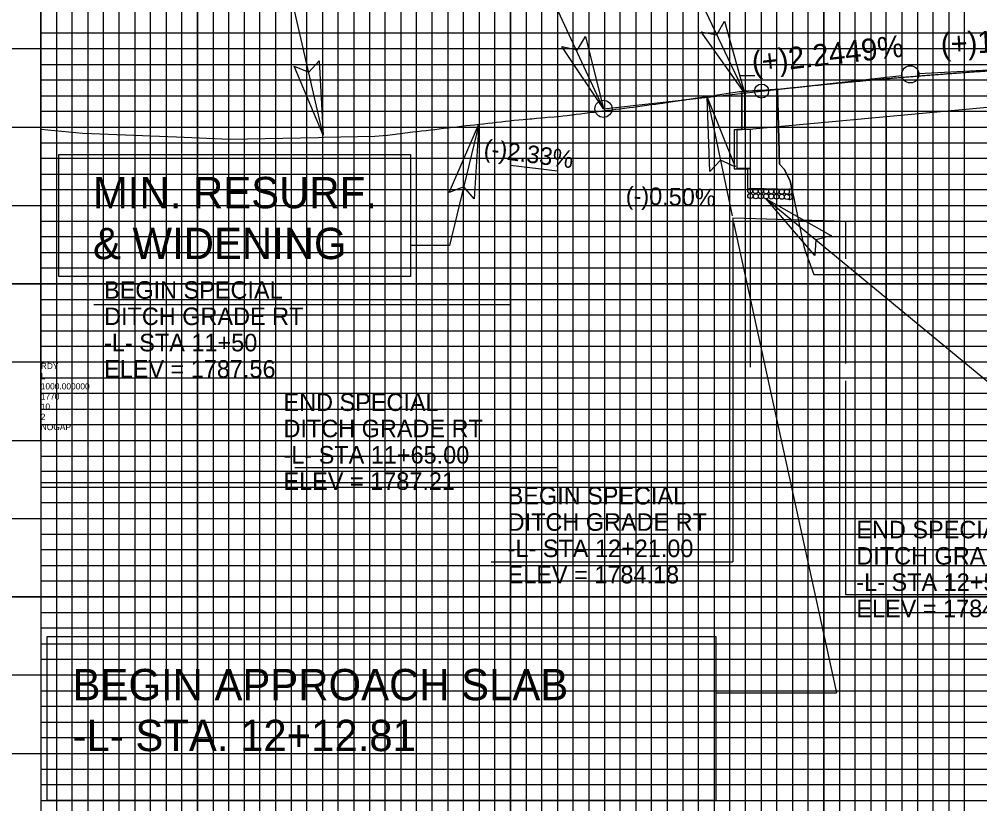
# Model space of a CAD drawing. Extents: x 572269 to 579912, y -56875 to -49627.
# Drawn here: x 573877.8 to 574184.5, y -53513.8 to -53263.2 of the extents above; entities that cross this region are included whole.
import ezdxf

# ---------------------------------------------------------------- set-up
doc = ezdxf.new("R2010")
doc.units = 0
for name, color, linetype in [('Exist Profile Cell', 7, 'Continuous'), ('Exist Vertical Profile Ground Line', 7, 'Continuous'), ('Pattern 9', 7, 'Continuous'), ('Prop Grid Mask', 7, 'Continuous'), ('Prop Hatching', 7, 'Continuous'), ('Prop PFL Text', 7, 'Continuous'), ('Prop Rip Rap Related Quantities Text', 7, 'Continuous'), ('Prop Roadway Bridge', 7, 'Continuous'), ('Prop Vertical Profile Curve Label', 7, 'Continuous'), ('Prop Vertical Profile Ditch Grade Right', 7, 'Continuous'), ('Prop Vertical Profile Ditch Grade Right Label', 7, 'Continuous'), ('Prop Vertical Profile Grade', 7, 'Continuous'), ('Prop Vertical Profile Grade Label', 7, 'Continuous'), ('Prop VPI Label', 7, 'Continuous'), ('Scratch_Level_0', 7, 'Continuous'), ('Scratch_Level_6', 7, 'Continuous'), ('Sheet Cutting Line CELL', 7, 'Continuous'), ('Sheet DOT Grid CELL', 7, 'Continuous'), ('Sheet Layout Profile Border', 7, 'Continuous'), ('Sheet Profile Grid Major CELL', 7, 'Continuous'), ('Sheet Profile Grid Middle CELL', 7, 'Continuous'), ('Sheet Profile Grid Minor CELL', 7, 'Continuous'), ('Typical Terminator CELL', 7, 'Continuous')]:
    doc.layers.add(name, color=color, linetype=linetype)

# ---------------------------------------------------------------- blocks, each defined once
blk = doc.blocks.new('TERMINATOR')
at = {"layer": 'Typical Terminator CELL'}
blk.add_lwpolyline([(-0.4687, 0.0807), (0, 0), (-0.4713, -0.0833), (-0.4114, 0)], close=True, dxfattribs=at)
blk = doc.blocks.new('PROFILE SHEET SINGLE')
at = {"layer": 'Sheet DOT Grid CELL'}
for p, q in [((1, 21), (1, 0.5)), ((2, 21), (2, 0.5)), ((3, 21), (3, 0.5)), ((4, 21), (4, 0.5)), ((5, 21), (5, 0.5)), ((6, 21), (6, 0.5)), ((0, 10.5), (30, 10.5)), ((0, 9.5), (30, 9.5)), ((0, 8.5), (30, 8.5)), ((0, 7.5), (30, 7.5)), ((0, 6.5), (30, 6.5))]:
    blk.add_line(p, q, dxfattribs=at)
at = {"layer": 'Sheet Profile Grid Major CELL'}
for points in [[(1, 21), (1, 0.5), (2, 0.5), (2, 21)], [(3, 21), (3, 0.5), (4, 0.5), (4, 21)], [(5, 21), (5, 0.5), (6, 0.5), (6, 21)], [(30, 9.5), (0, 9.5), (0, 10.5), (30, 10.5)], [(30, 7.5), (0, 7.5), (0, 8.5), (30, 8.5)], [(30, 5.5), (0, 5.5), (0, 6.5), (30, 6.5)]]:
    blk.add_lwpolyline(points, dxfattribs=at)
at = {"layer": 'Sheet Profile Grid Middle CELL'}
for points in [[(1.5, 0.5), (1.5, 21)], [(2.5, 21), (2.5, 0.5), (3.5, 0.5), (3.5, 21)], [(4.5, 21), (4.5, 0.5), (5.5, 0.5), (5.5, 21)], [(6.5, 21), (6.5, 0.5), (7.5, 0.5), (7.5, 21)], [(30, 11), (0, 11), (0, 10), (30, 10)], [(30, 9), (0, 9), (0, 8), (30, 8)], [(30, 7), (0, 7), (0, 6), (30, 6)]]:
    blk.add_lwpolyline(points, dxfattribs=at)
at = {"layer": 'Sheet Profile Grid Minor CELL'}
for points in [[(1.1, 21), (1.1, 0.5), (1.2, 0.5), (1.2, 21)], [(1.3, 21), (1.3, 0.5), (1.4, 0.5), (1.4, 21)], [(1.6, 21), (1.6, 0.5), (1.7, 0.5), (1.7, 21)], [(1.8, 21), (1.8, 0.5), (1.9, 0.5), (1.9, 21)], [(2.1, 21), (2.1, 0.5), (2.2, 0.5), (2.2, 21)], [(2.3, 21), (2.3, 0.5), (2.4, 0.5), (2.4, 21)], [(2.6, 21), (2.6, 0.5), (2.7, 0.5), (2.7, 21)], [(2.8, 21), (2.8, 0.5), (2.9, 0.5), (2.9, 21)], [(3.1, 21), (3.1, 0.5), (3.2, 0.5), (3.2, 21)], [(3.3, 21), (3.3, 0.5), (3.4, 0.5), (3.4, 21)], [(3.6, 21), (3.6, 0.5), (3.7, 0.5), (3.7, 21)], [(3.8, 21), (3.8, 0.5), (3.9, 0.5), (3.9, 21)], [(4.1, 21), (4.1, 0.5), (4.2, 0.5), (4.2, 21)], [(4.3, 21), (4.3, 0.5)], [(4.3, 0.5), (4.4, 0.5), (4.4, 21)], [(4.6, 21), (4.6, 0.5), (4.7, 0.5), (4.7, 21)], [(4.8, 21), (4.8, 0.5), (4.9, 0.5), (4.9, 21)], [(5.1, 21), (5.1, 0.5), (5.2, 0.5), (5.2, 21)], [(5.3, 21), (5.3, 0.5), (5.4, 0.5), (5.4, 21)], [(5.6, 21), (5.6, 0.5), (5.7, 0.5), (5.7, 21)], [(5.8, 21), (5.8, 0.5), (5.9, 0.5), (5.9, 21)], [(6.1, 21), (6.1, 0.5), (6.2, 0.5), (6.2, 21)], [(6.3, 21), (6.3, 0.5), (6.4, 0.5), (6.4, 21)], [(6.6, 21), (6.6, 0.5), (6.7, 0.5), (6.7, 21)], [(6.8, 21), (6.8, 0.5), (6.9, 0.5), (6.9, 21)], [(29, 11.1), (1, 11.1), (1, 10.9), (29, 10.9)], [(29, 10.8), (1, 10.8), (1, 10.7), (29, 10.7)], [(29, 10.6), (1, 10.6)], [(1, 10.4), (29, 10.4)], [(29, 10.3), (1, 10.3), (1, 10.2), (29, 10.2)], [(29, 10.1), (1, 10.1), (1, 9.9), (29, 9.9)], [(29, 9.8), (1, 9.8), (1, 9.7), (29, 9.7)], [(29, 9.6), (1, 9.6), (1, 9.4), (29, 9.4)], [(29, 9.3), (1, 9.3), (1, 9.2), (29, 9.2)], [(29, 9.1), (1, 9.1), (1, 8.9), (29, 8.9)], [(29, 8.8), (1, 8.8), (1, 8.7), (29, 8.7)], [(29, 8.6), (1, 8.6), (1, 8.4), (29, 8.4)], [(29, 8.3), (1, 8.3), (1, 8.2), (29, 8.2)], [(29, 8.1), (1, 8.1), (1, 7.9), (29, 7.9)], [(29, 7.8), (1, 7.8), (1, 7.7), (29, 7.7)], [(29, 7.6), (1, 7.6), (1, 7.4), (29, 7.4)], [(29, 7.3), (1, 7.3), (1, 7.2), (29, 7.2)], [(29, 7.1), (1, 7.1), (1, 6.9), (29, 6.9)], [(29, 6.8), (1, 6.8), (1, 6.7), (29, 6.7)], [(29, 6.6), (1, 6.6), (1, 6.4), (29, 6.4)], [(29, 6.3), (1, 6.3), (1, 6.2), (29, 6.2)]]:
    blk.add_lwpolyline(points, dxfattribs=at)

msp = doc.modelspace()

# ---------------------------------------------------------------- linework, layer by layer
at = {"layer": 'Exist Profile Cell'}
for q in [(573884.69, -53147.71), (574399.37, -53397.71), (573884.69, -53397.71)]:
    msp.add_line((573884.69, -53397.71), q, dxfattribs=at)
at = {"layer": 'Exist Vertical Profile Ground Line'}
for points in [[(573884.69, -53298.32), (573889.23, -53298.76), (573898.12, -53299.62), (573928.04, -53300.85), (573945.11, -53301.55), (573973.3, -53301.02), (573975.11, -53300.91), (573991.41, -53300.56), (573993.98, -53300.4), (573995.42, -53300.23), (574003.48, -53299.25), (574004.89, -53299.08), (574006.3, -53298.91), (574007.71, -53298.74), (574009.12, -53298.57), (574010.52, -53298.41), (574011.93, -53298.24), (574013.34, -53298.07), (574014.75, -53297.91), (574016.16, -53297.74), (574017.57, -53297.57), (574018.98, -53297.41), (574020.54, -53297.23), (574021.8, -53297.09), (574023.21, -53296.93), (574024.62, -53296.77), (574026.03, -53296.61), (574027.44, -53296.46), (574028.85, -53296.3), (574030.26, -53296.14), (574031.67, -53295.98), (574033.08, -53295.82), (574034.49, -53295.66), (574035.01, -53295.61), (574035.9, -53295.53), (574037.31, -53295.4), (574038.72, -53295.27), (574040.12, -53295.14), (574040.81, -53295.08), (574041.53, -53295.01), (574042.94, -53294.87), (574044.35, -53294.73), (574045.76, -53294.59), (574047.17, -53294.47), (574048.12, -53294.49), (574048.58, -53294.44), (574049.99, -53294.29), (574051.4, -53294.13), (574052.81, -53293.98), (574054.22, -53293.82), (574054.54, -53293.78), (574055.05, -53293.64), (574055.63, -53293.58), (574057.04, -53293.41), (574058.45, -53293.25), (574059.86, -53293.08), (574061.54, -53292.89), (574062.68, -53292.7), (574063.17, -53292.62), (574064.09, -53292.51), (574065.5, -53292.34), (574066.91, -53292.17), (574068.32, -53292), (574069.72, -53291.83), (574071.13, -53291.64), (574072.54, -53291.46), (574073.95, -53291.28), (574075.36, -53291.1), (574076.77, -53290.92), (574078.18, -53290.72), (574079.59, -53290.52), (574081, -53290.33), (574082.41, -53290.14), (574083.31, -53290.01), (574083.82, -53289.96), (574085.23, -53289.75), (574086.64, -53289.54), (574088.05, -53289.34), (574089.46, -53289.13), (574090.55, -53288.97), (574090.87, -53288.92), (574092.28, -53288.71), (574093.69, -53288.49), (574095.1, -53288.27), (574096.51, -53288.06), (574097.3, -53287.94), (574098.07, -53287.86), (574099.32, -53287.66), (574100.73, -53287.44), (574102.14, -53287.21), (574103.55, -53286.99), (574104.96, -53286.76), (574106.37, -53286.53), (574107.78, -53286.3), (574108.41, -53286.31), (574109.19, -53286.27), (574110.6, -53286.2), (574112.01, -53286.12), (574113.42, -53286.05), (574114.83, -53285.97), (574116.24, -53285.89), (574117.65, -53285.82), (574119.06, -53285.72), (574119.95, -53285.57), (574120.55, -53309.54), (574122.17, -53311.24), (574123.29, -53313.5), (574123.96, -53314.87), (574124.7, -53318.37), (574126.11, -53325.08), (574127.52, -53331.81), (574128.35, -53335.77), (574128.92, -53337.47), (574130.33, -53341.53), (574131.58, -53344.81), (574131.96, -53344.81), (574133.15, -53344.81), (574134.56, -53344.81), (574135.97, -53344.81), (574137.38, -53344.81), (574138.79, -53344.81), (574140.2, -53344.81), (574141.61, -53344.81), (574143.02, -53344.81), (574144.43, -53344.81), (574145.54, -53344.81), (574145.84, -53344.81), (574147.25, -53344.81), (574148.66, -53344.81), (574150.07, -53344.81), (574151.48, -53344.81), (574152.07, -53344.81), (574152.89, -53344.81), (574153.83, -53344.81), (574154.3, -53344.81), (574155.71, -53344.81), (574164.26, -53344.81), (574189.32, -53344.81)], [(573884.69, -53298.32), (573889.23, -53298.76), (573898.12, -53299.62), (573928.04, -53300.85), (573945.11, -53301.55), (573973.3, -53301.02), (573975.11, -53300.91), (573991.41, -53300.56), (573993.98, -53300.4), (573995.42, -53300.23), (574003.48, -53299.25), (574004.89, -53299.08), (574006.3, -53298.91), (574007.71, -53298.74), (574009.12, -53298.57), (574010.52, -53298.41), (574011.93, -53298.24), (574013.34, -53298.07), (574014.75, -53297.91), (574016.16, -53297.74), (574017.57, -53297.57), (574018.98, -53297.41), (574020.54, -53297.23), (574021.8, -53297.09), (574023.21, -53296.93), (574024.62, -53296.77), (574026.03, -53296.61), (574027.44, -53296.46), (574028.85, -53296.3), (574030.26, -53296.14), (574031.67, -53295.98), (574033.08, -53295.82), (574034.49, -53295.66), (574035.01, -53295.61), (574035.9, -53295.53), (574037.31, -53295.4), (574038.72, -53295.27), (574040.12, -53295.14), (574040.81, -53295.08), (574041.53, -53295.01), (574042.94, -53294.87), (574044.35, -53294.73), (574045.76, -53294.59), (574047.17, -53294.47), (574048.12, -53294.49), (574048.58, -53294.44), (574049.99, -53294.29), (574051.4, -53294.13), (574052.81, -53293.98), (574054.22, -53293.82), (574054.54, -53293.78), (574055.05, -53293.64), (574055.63, -53293.58), (574057.04, -53293.41), (574058.45, -53293.25), (574059.86, -53293.08), (574061.54, -53292.89), (574062.68, -53292.7), (574063.17, -53292.62), (574064.09, -53292.51), (574065.5, -53292.34), (574066.91, -53292.17), (574068.32, -53292), (574069.72, -53291.83), (574071.13, -53291.64), (574072.54, -53291.46), (574073.95, -53291.28), (574075.36, -53291.1), (574076.77, -53290.92), (574078.18, -53290.72), (574079.59, -53290.52), (574081, -53290.33), (574082.41, -53290.14), (574083.31, -53290.01), (574083.82, -53289.96), (574085.23, -53289.75), (574086.64, -53289.54), (574088.05, -53289.34), (574089.46, -53289.13), (574090.55, -53288.97), (574090.87, -53288.92), (574092.28, -53288.71), (574093.69, -53288.49), (574095.1, -53288.27), (574096.51, -53288.06), (574097.3, -53287.94), (574098.07, -53287.86), (574099.32, -53287.66), (574100.73, -53287.44), (574102.14, -53287.21), (574103.55, -53286.99), (574104.96, -53286.76), (574106.37, -53286.53), (574107.78, -53286.3), (574108.41, -53286.31), (574109.19, -53286.27), (574110.6, -53286.2), (574112.01, -53286.12), (574113.42, -53286.05), (574114.83, -53285.97), (574116.24, -53285.89), (574117.65, -53285.82), (574119.06, -53285.72), (574119.95, -53285.57), (574120.55, -53309.54), (574122.17, -53311.24), (574123.29, -53313.5), (574123.96, -53314.87), (574124.7, -53318.37), (574125.99, -53324.54)]]:
    msp.add_lwpolyline(points, dxfattribs=at)
at = {"layer": 'Pattern 9'}
for p, q in [((574108.5, -53286.36), (574108.5, -53286.9)), ((574108.5, -53286.9), (574108.5, -53298.54)), ((574109.43, -53286.26), (574109.43, -53298.44)), ((574112.49, -53286.15), (574111.08, -53286.23)), ((574113.9, -53286.08), (574112.49, -53286.15)), ((574115.31, -53286), (574113.9, -53286.08)), ((574119.96, -53285.62), (574118.13, -53285.82)), ((574120.55, -53309.54), (574119.96, -53285.62)), ((574108.5, -53298.54), (574106.07, -53298.54)), ((574106.07, -53298.54), (574106.07, -53311.04)), ((574109.43, -53298.44), (574107, -53298.44)), ((574107, -53298.44), (574107, -53310.94)), ((574106.07, -53311.04), (574110.32, -53311.04)), ((574107, -53310.94), (574111.25, -53310.94)), ((574110.32, -53311.04), (574110.32, -53317.32)), ((574111.25, -53310.94), (574111.25, -53317.21)), ((574122.17, -53311.24), (574120.55, -53309.54)), ((574110.32, -53317.32), (574124.52, -53317.55)), ((574111.25, -53317.21), (574124.52, -53317.55))]:
    msp.add_line(p, q, dxfattribs=at)
for points in [[(574111.08, -53286.23), (574109.67, -53286.3), (574108.5, -53286.36)], [(574124.52, -53317.55), (574123.96, -53314.87), (574123.29, -53313.5), (574122.17, -53311.24), (574120.55, -53309.54), (574119.95, -53285.57), (574119.06, -53285.72), (574117.65, -53285.82), (574116.24, -53285.89), (574114.83, -53285.97), (574113.42, -53286.05), (574112.01, -53286.12), (574110.6, -53286.2), (574109.43, -53286.26)], [(574118.13, -53285.82), (574116.72, -53285.92), (574115.31, -53286)], [(574124.52, -53317.55), (574123.96, -53314.87), (574122.99, -53312.98), (574122.17, -53311.24)]]:
    msp.add_lwpolyline(points, dxfattribs=at)
at = {"layer": 'Prop Grid Mask'}
for points in [[(573890.47, -53306.48), (574002.78, -53306.48), (574002.78, -53345.37), (573890.47, -53345.37)], [(573886.69, -53460.3), (574100.21, -53460.3), (574100.21, -53512.66), (573886.69, -53512.66)]]:
    msp.add_lwpolyline(points, close=True, dxfattribs=at)
at = {"layer": 'Prop Hatching'}
msp.add_line((574109.43, -53286.8), (574109.43, -53298.44), dxfattribs=at)
msp.add_lwpolyline([(574109.43, -53286.26), (574110.6, -53286.2), (574112.01, -53286.12), (574113.42, -53286.05), (574114.83, -53285.97), (574116.24, -53285.89), (574117.65, -53285.82), (574119.06, -53285.72), (574119.95, -53285.57), (574120.55, -53309.54), (574122.17, -53311.24), (574123.29, -53313.5), (574123.96, -53314.87), (574124.52, -53317.55)], dxfattribs=at)
at = {"layer": 'Prop PFL Text'}
for p, q in [((573974.87, -53300.26), (573900.84, -52978.52)), ((574064.36, -53291.86), (573958.57, -53063.91)), ((574109.43, -53286.8), (574040.04, -53140.99)), ((574097.5, -53288.14), (574105.46, -53326.06)), ((574024.62, -53296.77), (574015.16, -53335.45)), ((574116.31, -53320.63), (574258.52, -53437.99)), ((574105.92, -53328.15), (574138.83, -53478.37)), ((574015.16, -53335.45), (574002.78, -53335.45)), ((574100.21, -53478.37), (574138.83, -53478.37))]:
    msp.add_line(p, q, dxfattribs=at)
at = {"layer": 'Prop Rip Rap Related Quantities Text'}
for centre in [(574111.25, -53318.03), (574112.95, -53318.12), (574114.64, -53318.14), (574116.29, -53318.16), (574117.94, -53318.19), (574119.6, -53318.24), (574121.28, -53318.27), (574122.95, -53318.33), (574111.27, -53319.68), (574112.98, -53319.77), (574114.66, -53319.79), (574116.31, -53319.81), (574117.97, -53319.84), (574119.63, -53319.89), (574121.3, -53319.91), (574122.97, -53319.98)]:
    msp.add_circle(centre, 0.82, dxfattribs=at)
for centre, start, end in [((574123.85, -53318.36), 235.0346, 121.9914), ((574123.85, -53318.36), 106.2813, 107.3165), ((574123.87, -53320), 235.0346, 121.9914)]:
    msp.add_arc(centre, 0.82, start, end, dxfattribs=at)
at = {"layer": 'Prop Roadway Bridge'}
for p, q in [((574108.09, -53281.21), (574112.65, -53281.21)), ((574108.5, -53298.56), (574108.5, -53286.89)), ((574109.69, -53298.44), (574210.88, -53289.17)), ((574154.69, -53294.03), (574154.69, -53392.81)), ((574107, -53298.44), (574107, -53310.94)), ((574111.25, -53298.44), (574107, -53298.44)), ((574111.25, -53298.44), (574111.25, -53310.94)), ((574111.25, -53310.94), (574107, -53310.94)), ((574111.25, -53310.94), (574111.25, -53374.32)), ((574111.25, -53317.21), (574124.52, -53317.55))]:
    msp.add_line(p, q, dxfattribs=at)
at = {"layer": 'Prop Vertical Profile Curve Label'}
msp.add_circle((574114.86, -53286.19), 2.25, dxfattribs=at)
at = {"layer": 'Prop Vertical Profile Ditch Grade Right'}
msp.add_line((574034.69, -53309.9), (574049.69, -53311.66), dxfattribs=at)
msp.add_lwpolyline([(574105.69, -53326.71), (574141.69, -53327.71)], dxfattribs=at)
at = {"layer": 'Prop Vertical Profile Ditch Grade Right Label'}
for p, q in [((574034.69, -53309.9), (574034.69, -53354.29)), ((574049.69, -53311.66), (574049.69, -53406.38)), ((574105.69, -53326.71), (574105.69, -53436.49)), ((574141.69, -53327.71), (574141.69, -53339.79)), ((574141.69, -53342.31), (574141.69, -53373.2)), ((573901.63, -53354.29), (574034.69, -53354.29)), ((574141.69, -53378.7), (574141.69, -53446.92)), ((573965.81, -53406.38), (574049.69, -53406.38)), ((574028.54, -53436.49), (574105.69, -53436.49)), ((574141.69, -53446.92), (574218.83, -53446.92))]:
    msp.add_line(p, q, dxfattribs=at)
at = {"layer": 'Prop Vertical Profile Grade'}
msp.add_line((574064.36, -53291.86), (574114.86, -53286.19), dxfattribs=at)
msp.add_spline([(574114.86, -53286.19), (574116.76, -53285.98), (574118.66, -53285.77), (574120.56, -53285.56), (574122.46, -53285.36), (574124.36, -53285.15), (574126.26, -53284.95), (574128.16, -53284.75), (574130.06, -53284.56), (574131.96, -53284.36), (574133.86, -53284.17), (574135.76, -53283.98), (574137.66, -53283.79), (574139.56, -53283.61), (574141.46, -53283.43), (574143.36, -53283.25), (574145.26, -53283.07), (574147.16, -53282.89), (574149.06, -53282.72), (574150.96, -53282.55), (574152.86, -53282.38), (574154.76, -53282.21), (574156.66, -53282.05), (574158.56, -53281.89), (574160.46, -53281.73), (574162.36, -53281.57), (574164.26, -53281.41), (574166.16, -53281.26), (574168.06, -53281.11), (574169.96, -53280.96), (574171.86, -53280.82), (574173.76, -53280.67), (574175.66, -53280.53), (574177.56, -53280.39), (574179.46, -53280.25), (574181.36, -53280.12), (574183.26, -53279.99), (574185.16, -53279.86), (574187.06, -53279.73), (574188.96, -53279.6), (574190.86, -53279.48), (574192.76, -53279.36), (574194.66, -53279.24), (574196.56, -53279.12), (574198.46, -53279.01), (574200.36, -53278.89), (574202.26, -53278.79), (574204.16, -53278.68), (574206.06, -53278.57), (574207.96, -53278.47), (574209.86, -53278.37)], degree=3, dxfattribs=at)
at = {"layer": 'Prop VPI Label'}
for p, q in [((574114.86, -53286.19), (574159.62, -53281.17)), ((574209.86, -53278.37), (574165.1, -53280.71))]:
    msp.add_line(p, q, dxfattribs=at)
for centre in [(574162.36, -53280.86), (574064.36, -53291.86)]:
    msp.add_circle(centre, 2.75, dxfattribs=at)
at = {"layer": 'Scratch_Level_0'}
for p, q in [((575012.91, -53411.24), (573884.69, -53411.24)), ((573884.69, -53497.71), (575215.07, -53497.71))]:
    msp.add_line(p, q, dxfattribs=at)
at = {"layer": 'Scratch_Level_6'}
msp.add_line((576826.8, -53347.71), (572993.85, -53347.71), dxfattribs=at)
at = {"layer": 'Sheet Layout Profile Border'}
msp.add_lwpolyline([(573884.69, -52772.71), (573884.69, -53797.71), (575284.69, -53797.71), (575284.69, -52910.26), (575134.64, -52910.26), (575134.64, -52772.71)], close=True, dxfattribs=at)

# ---------------------------------------------------------------- block references
at = {"layer": 'Prop PFL Text'}
for p, xscale, yscale, rotation in [((574109.43, -53286.8), 50.00000000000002, 50.00000000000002, -64.53263926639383), ((574064.36, -53291.86), 50, 50.00000000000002, -66.40759669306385), ((573974.87, -53300.26), 50.00000000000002, 50.000000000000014, -77.16362394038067), ((574097.5, -53288.14), 50.00000000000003, 50.00000000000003, 101.81758454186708), ((574024.62, -53296.77), 50.00000000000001, 50.00000000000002, 76.27287940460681), ((574116.31, -53320.63), 50.00000000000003, 50.00000000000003, 140.4620536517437)]:
    msp.add_blockref('TERMINATOR', p, dxfattribs=dict(at, xscale=xscale, yscale=yscale, rotation=rotation))
at = {"layer": 'Sheet Cutting Line CELL', "xscale": 50, "yscale": 50}
msp.add_blockref('PROFILE SHEET SINGLE', (573834.69, -53822.71), dxfattribs=at)

# ---------------------------------------------------------------- texts
at = {"layer": 'Exist Profile Cell'}
for s, p in [('RDY', (573884.69, -53374.96)), ('L', (573884.69, -53378.21)), ('1000.000000', (573884.69, -53381.46)), ('1770', (573884.69, -53384.71)), ('10', (573884.69, -53387.96)), ('2', (573884.69, -53391.21)), ('NOGAP', (573884.69, -53394.46))]:
    msp.add_text(s, height=2, dxfattribs=at).set_placement(p)
at = {"layer": 'Prop PFL Text'}
for s, p in [('MIN. RESURF.', (573901.36, -53323.6)), ('& WIDENING', (573901.36, -53339.85)), ('BEGIN APPROACH SLAB', (573894.84, -53480.69)), ('-L- STA. 12+12.81', (573894.84, -53496.94))]:
    msp.add_text(s, height=10, dxfattribs=at).set_placement(p)
at = {"layer": 'Prop Vertical Profile Ditch Grade Right'}
for s, rotation, p in [('(-)2.33%', 352.522, (574025.91, -53307.13)), ('(-)0.50%', 358.7082, (574071.43, -53322.36))]:
    msp.add_text(s, height=5.6, rotation=rotation, dxfattribs=at).set_placement(p)
at = {"layer": 'Prop Vertical Profile Ditch Grade Right Label'}
for s, p in [('BEGIN SPECIAL', (573904.91, -53352.5)), ('DITCH GRADE RT', (573904.91, -53360.9)), ('-L- STA 11+50', (573904.91, -53369.3)), ('ELEV = 1787.56', (573904.91, -53377.7)), ('END SPECIAL', (573962.2, -53388.33)), ('DITCH GRADE RT', (573962.2, -53396.73)), ('-L- STA 11+65.00', (573962.2, -53405.13)), ('ELEV = 1787.21', (573962.2, -53413.53)), ('BEGIN SPECIAL', (574033.77, -53418.19)), ('DITCH GRADE RT', (574033.77, -53426.59)), ('END SPECIAL', (574145.12, -53428.99)), ('-L- STA 12+21.00', (574033.77, -53434.99)), ('DITCH GRADE RT', (574145.12, -53437.39)), ('ELEV = 1784.18', (574033.77, -53443.39)), ('-L- STA 12+57.00', (574145.12, -53445.79)), ('ELEV = 1784.00', (574145.12, -53454.19))]:
    msp.add_text(s, height=5.6, dxfattribs=at).set_placement(p)
at = {"layer": 'Prop Vertical Profile Grade Label'}
for s, rotation, p in [('(+)1.0483%', 3.0005, (574172.25, -53274.72)), ('(+)2.2449%', 6.4044, (574112.13, -53280.59))]:
    msp.add_text(s, height=7, rotation=rotation, dxfattribs=at).set_placement(p)

doc.saveas('drawing.dxf')
